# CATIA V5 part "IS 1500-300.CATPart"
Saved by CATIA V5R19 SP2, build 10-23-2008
Part number: IS 1500-300
Bounding box of the stored display mesh (mm): x -37.351 to 37.351, y -37.351 to 37.351, z 0 to 710
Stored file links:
  C:\Users\Bora\Desktop\3D Katı model\IS serisi\IS 1500\IS 1500-300.CATPart
  C:\Program Files\Dassault Systemes\B19\intel_a\reffiles\standard\MetricThickPitch.txt
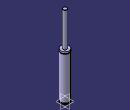
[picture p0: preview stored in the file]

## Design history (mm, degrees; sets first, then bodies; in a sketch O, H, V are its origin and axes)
Body1 (main body)
  Sketch1 on yz-plane, origin (0, 0, 0), H (0, 1, 0), V (0, 0, 1)
    point P1 (37.5, 391.5)
    point P2 (37.5, 386.5)
    point P5 (18, 709)
    point P7 (18, 709)
    point P12 (37.5, 386.5)
    point P13 (37.5, 391.5)
    arc A1 centre (37.5, 389) radius 2.5 from (37.5, 391.5) to (37.5, 386.5) ccw
    line L1 (37.5, 0) -> (37.5, 8)
    line L2 (18, 709) -> (18, 407)
    arc A2 centre (17, 709) radius 1 from (18, 709) to (17, 710) ccw
    line L3 (33.5, 13) -> (33.5, 8)
    line L4 (37.5, 13) -> (37.5, 386.5)
    line L5 (37.5, 391.5) -> (37.5, 407)
    line L6 (17, 710) -> (0, 710)
    point P15 (0, 710)
    line L7 (18, 407) -> (37.5, 407)
    line L8 (33.5, 13) -> (37.5, 13)
    line L9 (33.5, 8) -> (37.5, 8)
    line L10 (37.5, 0) -> (0, 0)
    coincidence: P15 V, P1 P13, P2 P12, P5 P7
    tangency: L6 A2
    horizontal: L7 H, L8 H, L10 H
    parallelism: L9 L8
  Shaft1: profile Sketch1, axis Sketch1.V, angle 360
  Sketch2 on face of Shaft1 from Sketch1.L10, origin (0, 0, 0), H (1, 0, 0), V (0, -1, 0)
    point P1 (20, 0)
    distance P1 V = 20
  Hole1: placed by Sketch2, at (20, 0, 0) direction (0, 0, 1), diameter 6.647, depth 13, threaded "M8", thread diameter 8, thread depth 13, pitch 1.25
  CircPattern1: of Hole1, instances 4, angular step 90, axis from xy-plane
